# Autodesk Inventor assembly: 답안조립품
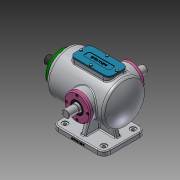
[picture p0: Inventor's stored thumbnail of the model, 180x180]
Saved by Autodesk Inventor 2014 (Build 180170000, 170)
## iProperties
Created: 2021-11
Part Number: 답안조립품
Document SubType Name: Assembly
Designer: kb542-04
Author: kb542-04
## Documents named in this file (14)
- C:\Users\kb542-04\Desktop\711106V1006\답안조립품.iam
- C:\Users\kb542-04\Desktop\711106V1006\베어링 6205.ipt
- 베어링 6205.ipt
- C:\Users\kb542-04\Desktop\711106V1006\본체.ipt
- C:\Users\kb542-04\Desktop\711106V1006\볼트 M4x0.7.ipt
- C:\Users\kb542-04\Desktop\711106V1006\부시.ipt
- C:\Users\kb542-04\Desktop\711106V1006\상부커버.ipt
- C:\Users\kb542-04\Desktop\711106V1006\슬라이드 커버.ipt
- C:\Users\kb542-04\Desktop\711106V1006\슬라이드.ipt
- C:\Users\kb542-04\Desktop\711106V1006\오일실.ipt
- 오일실.ipt
- C:\Users\kb542-04\Desktop\711106V1006\육각머리볼트 M4.ipt
- C:\Users\kb542-04\Desktop\711106V1006\축 커버.ipt
- C:\Users\kb542-04\Desktop\711106V1006\편심축.ipt
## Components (12 placed, 1 different names)
1. M4x0.7:3
2. M4x0.7:4
3. M4x0.7:5
4. M4x0.7:6
5. M4x0.7:2
6. M4x0.7:7
7. M4x0.7:8
8. M4x0.7:9
9. M4x0.7:1
10. M4x0.7:10
11. M4x0.7:11
12. M4x0.7:12
